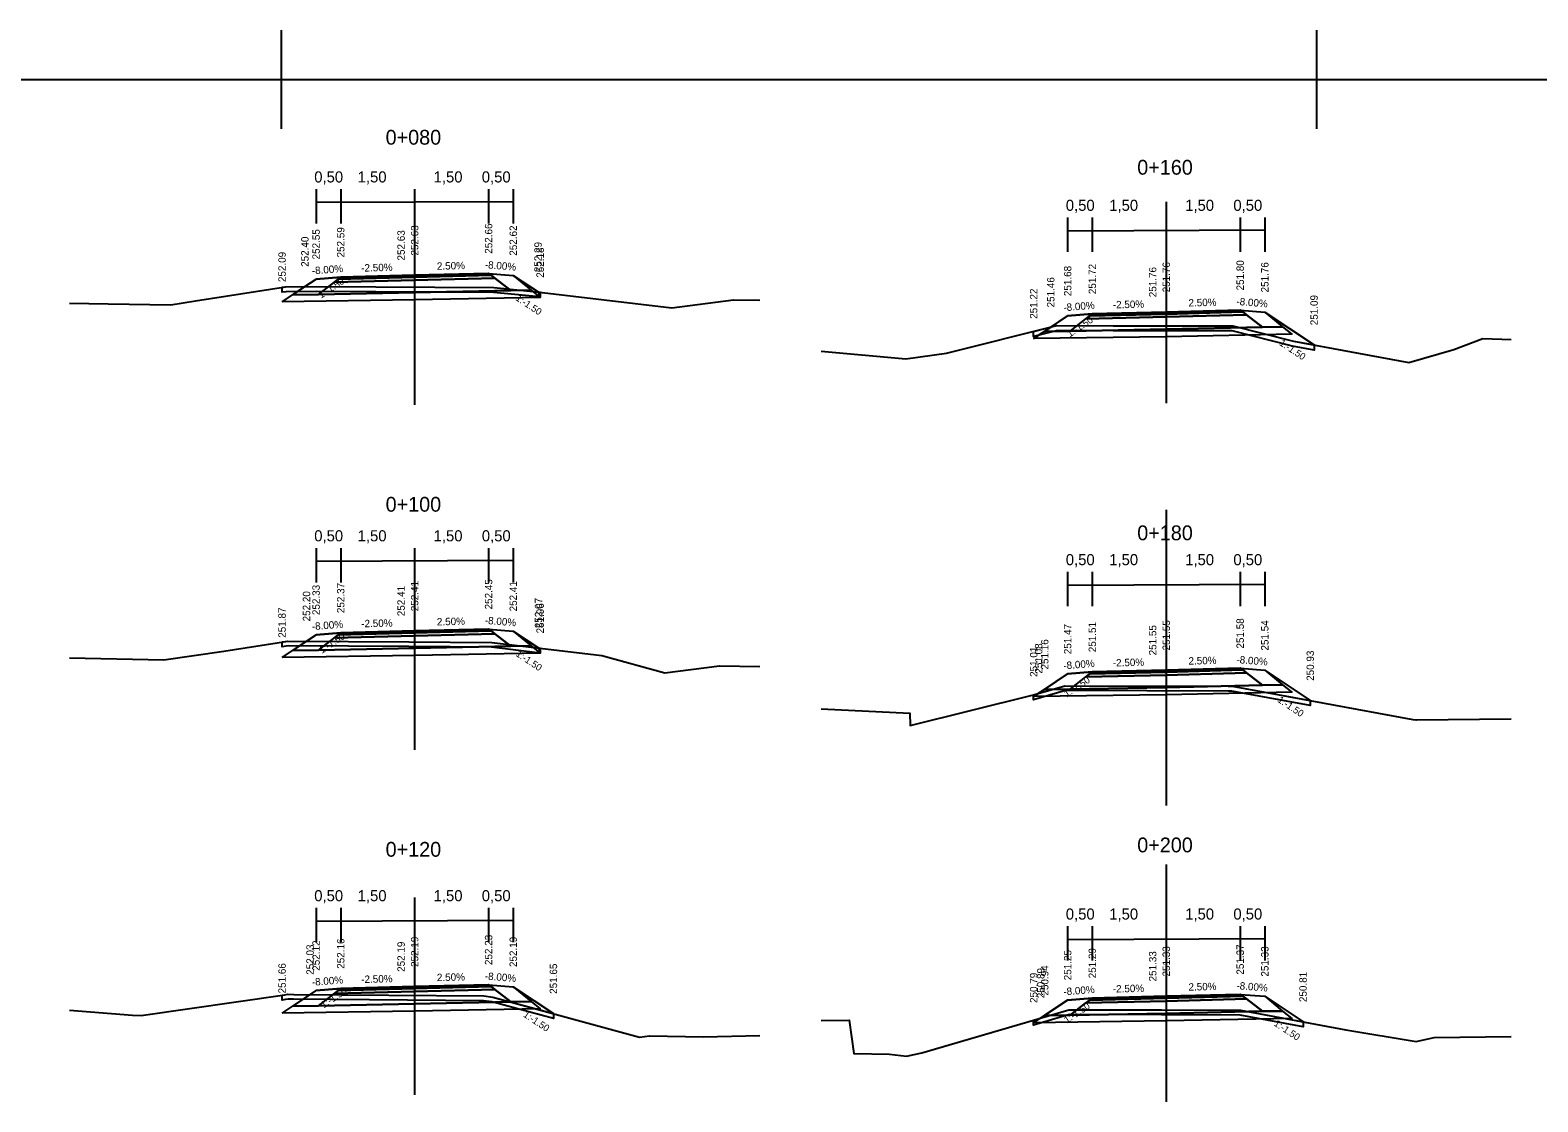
# Model space of a CAD drawing. Extents: x -552501 to -552394, y -1029983 to -1029892.
# Drawn here: x -552483.85 to -552453.26, y -1029914.09 to -1029892.35 of the extents above; entities that cross this region are included whole.
import ezdxf

# ---------------------------------------------------------------- set-up
doc = ezdxf.new("R2010")
doc.units = 0
for name, color, linetype in [('1', 7, 'Continuous'), ('16', 7, 'Continuous'), ('60', 7, 'Continuous'), ('9', 7, 'Continuous'), ('FORMATY', 7, 'Continuous'), ('Implicitní', 7, 'Continuous'), ('rámeček', 7, 'Continuous')]:
    doc.layers.add(name, color=color, linetype=linetype)

msp = doc.modelspace()

# ---------------------------------------------------------------- linework, layer by layer
for points in [[(-552478.74, -1029897.861), (-552478.277, -1029897.552), (-552478.05, -1029897.401), (-552477.55, -1029897.361), (-552476.05, -1029897.323), (-552474.55, -1029897.286), (-552474.05, -1029897.326), (-552473.547, -1029897.661), (-552473.504, -1029897.773)], [(-552483.05, -1029897.887), (-552482.271, -1029897.904), (-552480.995, -1029897.92), (-552480.495, -1029897.843), (-552478.667, -1029897.556), (-552478.034, -1029897.549), (-552474.445, -1029897.572), (-552473.576, -1029897.658), (-552470.831, -1029897.981), (-552469.585, -1029897.822), (-552469.05, -1029897.83)], [(-552463.493, -1029898.606), (-552463.146, -1029898.375), (-552462.803, -1029898.146), (-552462.303, -1029898.106), (-552460.803, -1029898.069), (-552459.303, -1029898.031), (-552458.803, -1029898.071), (-552457.804, -1029898.737)], [(-552467.803, -1029898.865), (-552466.089, -1029899.02), (-552465.26, -1029898.901), (-552463.022, -1029898.344), (-552461.878, -1029898.352), (-552459.452, -1029898.349), (-552458.221, -1029898.66), (-552455.879, -1029899.092), (-552454.971, -1029898.828), (-552454.377, -1029898.604), (-552453.803, -1029898.623)], [(-552478.74, -1029905.077), (-552478.244, -1029904.745), (-552478.05, -1029904.617), (-552477.55, -1029904.577), (-552476.05, -1029904.539), (-552474.55, -1029904.502), (-552474.05, -1029904.542), (-552473.537, -1029904.883), (-552473.504, -1029904.989)], [(-552483.05, -1029905.081), (-552481.14, -1029905.123), (-552479.921, -1029904.948), (-552478.626, -1029904.743), (-552476.165, -1029904.757), (-552474.484, -1029904.771), (-552472.254, -1029905.035), (-552470.974, -1029905.386), (-552469.867, -1029905.246), (-552469.05, -1029905.26)], [(-552463.493, -1029905.871), (-552463.392, -1029905.804), (-552463.268, -1029905.721), (-552462.803, -1029905.411), (-552462.303, -1029905.371), (-552460.803, -1029905.334), (-552459.303, -1029905.296), (-552458.803, -1029905.336), (-552457.881, -1029905.951)], [(-552467.803, -1029906.117), (-552466.006, -1029906.205), (-552465.997, -1029906.458), (-552463.523, -1029905.843), (-552462.863, -1029905.649), (-552459.545, -1029905.659), (-552459.464, -1029905.659), (-552455.799, -1029906.336), (-552455.741, -1029906.345), (-552455.726, -1029906.342), (-552453.803, -1029906.319)], [(-552483.05, -1029912.23), (-552481.776, -1029912.335), (-552481.601, -1029912.339), (-552478.683, -1029911.92), (-552478.621, -1029911.91), (-552478.504, -1029911.911), (-552474.644, -1029911.943), (-552474.462, -1029911.965), (-552471.489, -1029912.779), (-552471.283, -1029912.753), (-552470.189, -1029912.771), (-552469.05, -1029912.746)], [(-552478.74, -1029912.292), (-552478.172, -1029911.914), (-552478.05, -1029911.832), (-552477.55, -1029911.792), (-552476.05, -1029911.755), (-552474.55, -1029911.717), (-552474.05, -1029911.757), (-552473.235, -1029912.301)], [(-552463.493, -1029912.486), (-552463.348, -1029912.39), (-552463.268, -1029912.336), (-552462.803, -1029912.026), (-552462.303, -1029911.986), (-552460.803, -1029911.949), (-552459.303, -1029911.911), (-552458.803, -1029911.951), (-552458.028, -1029912.468)], [(-552467.803, -1029912.44), (-552467.237, -1029912.435), (-552467.138, -1029913.113), (-552466.415, -1029913.124), (-552466.069, -1029913.166), (-552465.761, -1029913.098), (-552462.778, -1029912.222), (-552460.901, -1029912.228), (-552459.294, -1029912.234), (-552457.16, -1029912.628), (-552455.73, -1029912.871), (-552455.37, -1029912.785), (-552453.803, -1029912.766)]]:
    msp.add_lwpolyline(points)
for points in [[(-552477.55, -1029897.361), (-552478.05, -1029897.401), (-552478.515, -1029897.711), (-552478.001, -1029897.711)], [(-552478.001, -1029897.711), (-552477.679, -1029897.461), (-552476.051, -1029897.423), (-552474.422, -1029897.38), (-552474.1, -1029897.63), (-552476.051, -1029897.673)], [(-552476.051, -1029897.363), (-552477.601, -1029897.401), (-552477.679, -1029897.461), (-552476.051, -1029897.423), (-552474.422, -1029897.38), (-552474.499, -1029897.32), (-552476.051, -1029897.363), (-552474.499, -1029897.32), (-552474.55, -1029897.286), (-552476.05, -1029897.323), (-552477.55, -1029897.361), (-552477.601, -1029897.401)], [(-552477.679, -1029897.461), (-552477.601, -1029897.401), (-552476.051, -1029897.363), (-552474.499, -1029897.32), (-552474.422, -1029897.38), (-552476.051, -1029897.423)], [(-552474.55, -1029897.286), (-552474.05, -1029897.326), (-552473.689, -1029897.623), (-552474.1, -1029897.63), (-552474.422, -1029897.38), (-552474.499, -1029897.32)], [(-552478.74, -1029897.567), (-552478.667, -1029897.556), (-552478.034, -1029897.549), (-552474.445, -1029897.572), (-552473.576, -1029897.658), (-552473.504, -1029897.666), (-552473.504, -1029897.767), (-552473.587, -1029897.757), (-552474.451, -1029897.672), (-552478.034, -1029897.649), (-552478.659, -1029897.656), (-552478.74, -1029897.669)], [(-552478.74, -1029897.861), (-552478.515, -1029897.711), (-552478.001, -1029897.711), (-552476.051, -1029897.673), (-552474.1, -1029897.63), (-552473.689, -1029897.623), (-552473.504, -1029897.773), (-552476.051, -1029897.823)], [(-552462.303, -1029898.106), (-552462.803, -1029898.146), (-552463.268, -1029898.456), (-552462.754, -1029898.456)], [(-552462.754, -1029898.456), (-552462.432, -1029898.206), (-552460.804, -1029898.169), (-552459.175, -1029898.125), (-552458.853, -1029898.375), (-552460.804, -1029898.419)], [(-552460.804, -1029898.109), (-552462.354, -1029898.146), (-552462.432, -1029898.206), (-552460.804, -1029898.169), (-552459.175, -1029898.125), (-552459.252, -1029898.065), (-552460.804, -1029898.109), (-552459.252, -1029898.065), (-552459.303, -1029898.031), (-552460.803, -1029898.069), (-552462.303, -1029898.106), (-552462.354, -1029898.146)], [(-552462.432, -1029898.206), (-552462.354, -1029898.146), (-552460.804, -1029898.109), (-552459.252, -1029898.065), (-552459.175, -1029898.125), (-552460.804, -1029898.169)], [(-552459.303, -1029898.031), (-552458.803, -1029898.071), (-552458.442, -1029898.369), (-552458.853, -1029898.375), (-552459.175, -1029898.125), (-552459.252, -1029898.065)], [(-552463.493, -1029898.461), (-552463.022, -1029898.344), (-552461.878, -1029898.352), (-552459.452, -1029898.349), (-552458.221, -1029898.66), (-552457.804, -1029898.737), (-552457.804, -1029898.839), (-552458.242, -1029898.758), (-552459.465, -1029898.449), (-552461.878, -1029898.452), (-552463.011, -1029898.444), (-552463.493, -1029898.564)], [(-552463.493, -1029898.606), (-552463.268, -1029898.456), (-552462.754, -1029898.456), (-552460.804, -1029898.419), (-552458.853, -1029898.375), (-552458.442, -1029898.369), (-552458.257, -1029898.519), (-552460.804, -1029898.569)], [(-552476.051, -1029904.579), (-552477.601, -1029904.617), (-552477.679, -1029904.677), (-552476.051, -1029904.639), (-552474.422, -1029904.596), (-552474.499, -1029904.536), (-552476.051, -1029904.579), (-552474.499, -1029904.536), (-552474.55, -1029904.502), (-552476.05, -1029904.539), (-552477.55, -1029904.577), (-552477.601, -1029904.617)], [(-552477.679, -1029904.677), (-552477.601, -1029904.617), (-552476.051, -1029904.579), (-552474.499, -1029904.536), (-552474.422, -1029904.596), (-552476.051, -1029904.639)], [(-552474.55, -1029904.502), (-552474.05, -1029904.542), (-552473.689, -1029904.839), (-552474.1, -1029904.846), (-552474.422, -1029904.596), (-552474.499, -1029904.536)], [(-552478.74, -1029904.761), (-552478.626, -1029904.743), (-552476.165, -1029904.757), (-552474.484, -1029904.771), (-552473.504, -1029904.887), (-552473.504, -1029904.988), (-552474.49, -1029904.871), (-552476.166, -1029904.857), (-552478.618, -1029904.843), (-552478.74, -1029904.863)], [(-552478.74, -1029905.077), (-552478.515, -1029904.927), (-552478.001, -1029904.927), (-552476.051, -1029904.889), (-552474.1, -1029904.846), (-552473.689, -1029904.839), (-552473.504, -1029904.989), (-552476.051, -1029905.039)], [(-552477.55, -1029904.577), (-552478.05, -1029904.617), (-552478.515, -1029904.927), (-552478.001, -1029904.927)], [(-552478.001, -1029904.927), (-552477.679, -1029904.677), (-552476.051, -1029904.639), (-552474.422, -1029904.596), (-552474.1, -1029904.846), (-552476.051, -1029904.889)], [(-552462.303, -1029905.371), (-552462.803, -1029905.411), (-552463.268, -1029905.721), (-552462.754, -1029905.721)], [(-552462.754, -1029905.721), (-552462.432, -1029905.471), (-552460.804, -1029905.434), (-552459.175, -1029905.39), (-552458.853, -1029905.64), (-552460.804, -1029905.684)], [(-552460.804, -1029905.374), (-552462.354, -1029905.411), (-552462.432, -1029905.471), (-552460.804, -1029905.434), (-552459.175, -1029905.39), (-552459.252, -1029905.33), (-552460.804, -1029905.374), (-552459.252, -1029905.33), (-552459.303, -1029905.296), (-552460.803, -1029905.334), (-552462.303, -1029905.371), (-552462.354, -1029905.411)], [(-552462.432, -1029905.471), (-552462.354, -1029905.411), (-552460.804, -1029905.374), (-552459.252, -1029905.33), (-552459.175, -1029905.39), (-552460.804, -1029905.434)], [(-552459.303, -1029905.296), (-552458.803, -1029905.336), (-552458.442, -1029905.634), (-552458.853, -1029905.64), (-552459.175, -1029905.39), (-552459.252, -1029905.33)], [(-552463.493, -1029905.871), (-552463.268, -1029905.721), (-552462.754, -1029905.721), (-552460.804, -1029905.684), (-552458.853, -1029905.64), (-552458.442, -1029905.634), (-552458.257, -1029905.784), (-552460.804, -1029905.834)], [(-552463.493, -1029905.834), (-552462.863, -1029905.649), (-552459.545, -1029905.659), (-552459.464, -1029905.659), (-552457.881, -1029905.951), (-552457.881, -1029906.053), (-552459.473, -1029905.759), (-552459.545, -1029905.759), (-552462.849, -1029905.749), (-552463.493, -1029905.938)], [(-552478.74, -1029911.928), (-552478.683, -1029911.92), (-552478.621, -1029911.91), (-552478.504, -1029911.911), (-552474.644, -1029911.943), (-552474.462, -1029911.965), (-552473.235, -1029912.301), (-552473.235, -1029912.404), (-552474.481, -1029912.063), (-552474.65, -1029912.043), (-552478.505, -1029912.011), (-552478.614, -1029912.01), (-552478.668, -1029912.019), (-552478.74, -1029912.029)], [(-552477.55, -1029911.792), (-552478.05, -1029911.832), (-552478.515, -1029912.142), (-552478.001, -1029912.142)], [(-552478.001, -1029912.142), (-552477.679, -1029911.892), (-552476.051, -1029911.855), (-552474.422, -1029911.811), (-552474.1, -1029912.061), (-552476.051, -1029912.105)], [(-552476.051, -1029911.795), (-552477.601, -1029911.832), (-552477.679, -1029911.892), (-552476.051, -1029911.855), (-552474.422, -1029911.811), (-552474.499, -1029911.751), (-552476.051, -1029911.795), (-552474.499, -1029911.751), (-552474.55, -1029911.717), (-552476.05, -1029911.755), (-552477.55, -1029911.792), (-552477.601, -1029911.832)], [(-552477.679, -1029911.892), (-552477.601, -1029911.832), (-552476.051, -1029911.795), (-552474.499, -1029911.751), (-552474.422, -1029911.811), (-552476.051, -1029911.855)], [(-552474.55, -1029911.717), (-552474.05, -1029911.757), (-552473.689, -1029912.055), (-552474.1, -1029912.061), (-552474.422, -1029911.811), (-552474.499, -1029911.751)], [(-552460.804, -1029911.989), (-552462.354, -1029912.026), (-552462.432, -1029912.086), (-552460.804, -1029912.049), (-552459.175, -1029912.005), (-552459.252, -1029911.945), (-552460.804, -1029911.989), (-552459.252, -1029911.945), (-552459.303, -1029911.911), (-552460.803, -1029911.949), (-552462.303, -1029911.986), (-552462.354, -1029912.026)], [(-552459.303, -1029911.911), (-552458.803, -1029911.951), (-552458.442, -1029912.249), (-552458.853, -1029912.255), (-552459.175, -1029912.005), (-552459.252, -1029911.945)], [(-552478.74, -1029912.292), (-552478.515, -1029912.142), (-552478.001, -1029912.142), (-552476.051, -1029912.105), (-552474.1, -1029912.061), (-552473.689, -1029912.055), (-552473.504, -1029912.205), (-552476.051, -1029912.255)], [(-552462.303, -1029911.986), (-552462.803, -1029912.026), (-552463.268, -1029912.336), (-552462.754, -1029912.336)], [(-552462.754, -1029912.336), (-552462.432, -1029912.086), (-552460.804, -1029912.049), (-552459.175, -1029912.005), (-552458.853, -1029912.255), (-552460.804, -1029912.299)], [(-552462.432, -1029912.086), (-552462.354, -1029912.026), (-552460.804, -1029911.989), (-552459.252, -1029911.945), (-552459.175, -1029912.005), (-552460.804, -1029912.049)], [(-552463.493, -1029912.432), (-552462.778, -1029912.222), (-552460.901, -1029912.228), (-552459.294, -1029912.234), (-552458.028, -1029912.468), (-552458.028, -1029912.569), (-552459.303, -1029912.334), (-552460.902, -1029912.328), (-552462.764, -1029912.322), (-552463.493, -1029912.536)], [(-552463.493, -1029912.486), (-552463.268, -1029912.336), (-552462.754, -1029912.336), (-552460.804, -1029912.299), (-552458.853, -1029912.255), (-552458.442, -1029912.249), (-552458.257, -1029912.399), (-552460.804, -1029912.449)]]:
    msp.add_lwpolyline(points, close=True)
at = {"layer": '60'}
for p, q in [((-552476.05, -1029895.949), (-552476.05, -1029899.949)), ((-552460.803, -1029895.831), (-552460.803, -1029899.916)), ((-552460.803, -1029902.082), (-552460.803, -1029908.082)), ((-552476.05, -1029902.949), (-552476.05, -1029906.949)), ((-552460.803, -1029909.279), (-552460.803, -1029914.092)), ((-552476.05, -1029909.949), (-552476.05, -1029913.949))]:
    msp.add_line(p, q, dxfattribs=at)
at = {"layer": '9'}
for p, q in [((-552478.05, -1029895.575), (-552478.05, -1029896.273)), ((-552477.55, -1029895.575), (-552477.55, -1029896.273)), ((-552476.05, -1029895.575), (-552476.05, -1029897.075)), ((-552474.55, -1029895.575), (-552474.55, -1029896.273)), ((-552474.05, -1029895.575), (-552474.05, -1029896.273)), ((-552462.803, -1029896.151), (-552462.803, -1029896.849)), ((-552462.303, -1029896.151), (-552462.303, -1029896.849)), ((-552460.803, -1029896.151), (-552460.803, -1029897.651)), ((-552459.303, -1029896.151), (-552459.303, -1029896.849)), ((-552458.803, -1029896.151), (-552458.803, -1029896.849)), ((-552478.05, -1029902.856), (-552478.05, -1029903.554)), ((-552477.55, -1029902.856), (-552477.55, -1029903.554)), ((-552476.05, -1029902.856), (-552476.05, -1029904.356)), ((-552474.55, -1029902.856), (-552474.55, -1029903.554)), ((-552474.05, -1029902.856), (-552474.05, -1029903.554)), ((-552462.803, -1029903.34), (-552462.803, -1029904.038)), ((-552462.303, -1029903.34), (-552462.303, -1029904.038)), ((-552460.803, -1029903.34), (-552460.803, -1029904.84)), ((-552459.303, -1029903.34), (-552459.303, -1029904.038)), ((-552458.803, -1029903.34), (-552458.803, -1029904.038)), ((-552478.05, -1029910.157), (-552478.05, -1029910.854)), ((-552477.55, -1029910.157), (-552477.55, -1029910.854)), ((-552476.05, -1029910.157), (-552476.05, -1029911.657)), ((-552474.55, -1029910.157), (-552474.55, -1029910.854)), ((-552474.05, -1029910.157), (-552474.05, -1029910.854)), ((-552462.803, -1029910.529), (-552462.803, -1029911.227)), ((-552462.303, -1029910.529), (-552462.303, -1029911.227)), ((-552460.803, -1029910.529), (-552460.803, -1029912.029)), ((-552459.303, -1029910.529), (-552459.303, -1029911.227)), ((-552458.803, -1029910.529), (-552458.803, -1029911.227))]:
    msp.add_line(p, q, dxfattribs=at)
at = {"layer": 'FORMATY'}
for p, q in [((-552478.755, -1029892.35), (-552478.755, -1029894.35)), ((-552457.755, -1029892.35), (-552457.755, -1029894.35)), ((-552479.755, -1029893.35), (-552477.755, -1029893.35)), ((-552458.755, -1029893.35), (-552456.755, -1029893.35))]:
    msp.add_line(p, q, dxfattribs=at)
at = {"layer": 'Implicitní'}
for p, q in [((-552478.04, -1029895.843), (-552474.05, -1029895.825)), ((-552462.793, -1029896.419), (-552458.803, -1029896.401)), ((-552478.04, -1029903.123), (-552474.05, -1029903.106)), ((-552462.793, -1029903.608), (-552458.803, -1029903.59)), ((-552478.04, -1029910.424), (-552474.05, -1029910.407)), ((-552462.793, -1029910.796), (-552458.803, -1029910.779))]:
    msp.add_line(p, q, dxfattribs=at)
at = {"layer": 'rámeček'}
msp.add_line((-552499.755, -1029893.35), (-552394.755, -1029893.35), dxfattribs=at)

# ---------------------------------------------------------------- texts
for rotation, p in [(33.6902, (-552477.947, -1029897.801)), (326.3098, (-552474.015, -1029897.818)), (33.6902, (-552462.758, -1029898.585)), (326.3098, (-552458.52, -1029898.729)), (33.6902, (-552477.931, -1029905.005)), (326.3098, (-552474.01, -1029905.037)), (33.6902, (-552462.819, -1029905.891)), (326.3098, (-552458.558, -1029905.968)), (33.6902, (-552477.895, -1029912.198)), (33.6902, (-552462.819, -1029912.506)), (326.3098, (-552473.859, -1029912.354)), (326.3098, (-552458.632, -1029912.534))]:
    msp.add_text('1:-1.50', height=0.14, rotation=rotation).set_placement(p)
at = {"layer": '1'}
for s, p in [('0+080', (-552476.639, -1029894.673)), ('0+160', (-552461.391, -1029895.282)), ('0+100', (-552476.639, -1029902.119)), ('0+180', (-552461.391, -1029902.698)), ('0+120', (-552476.639, -1029909.119)), ('0+200', (-552461.391, -1029909.03))]:
    msp.add_text(s, height=0.3, dxfattribs=at).set_placement(p)
at = {"layer": '16'}
for s, p in [('0,50', (-552478.087, -1029895.44)), ('1,50', (-552477.206, -1029895.44)), ('1,50', (-552475.665, -1029895.44)), ('0,50', (-552474.688, -1029895.44)), ('0,50', (-552462.84, -1029896.016)), ('1,50', (-552461.959, -1029896.016)), ('1,50', (-552460.418, -1029896.016)), ('0,50', (-552459.441, -1029896.016)), ('0,50', (-552478.087, -1029902.721)), ('1,50', (-552477.206, -1029902.721)), ('1,50', (-552475.665, -1029902.721)), ('0,50', (-552474.687, -1029902.721)), ('0,50', (-552462.84, -1029903.205)), ('1,50', (-552461.959, -1029903.205)), ('1,50', (-552460.418, -1029903.205)), ('0,50', (-552459.441, -1029903.205)), ('0,50', (-552478.087, -1029910.022)), ('1,50', (-552477.206, -1029910.022)), ('1,50', (-552475.665, -1029910.022)), ('0,50', (-552474.688, -1029910.022)), ('0,50', (-552462.84, -1029910.394)), ('1,50', (-552461.959, -1029910.394)), ('1,50', (-552460.418, -1029910.394)), ('0,50', (-552459.441, -1029910.394))]:
    msp.add_text(s, height=0.225, dxfattribs=at).set_placement(p)
for s, rotation, p in [('252.66', 90, (-552474.475, -1029896.886)), ('252.40', 90, (-552478.202, -1029897.152)), ('252.55', 90, (-552477.975, -1029897.001)), ('252.59', 90, (-552477.475, -1029896.961)), ('252.63', 90, (-552476.25, -1029897.023)), ('252.63', 90, (-552475.975, -1029896.923)), ('252.62', 90, (-552473.975, -1029896.926)), ('252.09', 90, (-552478.665, -1029897.461)), ('252.29', 90, (-552473.472, -1029897.261)), ('252.18', 90, (-552473.429, -1029897.373)), ('-8.00%', 4.5739, (-552478.131, -1029897.307)), ('-2.50%', 1.4321, (-552477.132, -1029897.25)), ('2.50%', 1.4321, (-552475.597, -1029897.212)), ('-8.00%', 355.4261, (-552474.631, -1029897.179)), ('251.68', 90, (-552462.728, -1029897.746)), ('251.72', 90, (-552462.228, -1029897.706)), ('251.76', 90, (-552461.003, -1029897.769)), ('251.76', 90, (-552460.728, -1029897.669)), ('251.80', 90, (-552459.228, -1029897.631)), ('251.76', 90, (-552458.728, -1029897.671)), ('251.46', 90, (-552463.071, -1029897.975)), ('251.22', 90, (-552463.418, -1029898.206)), ('-2.50%', 1.4321, (-552461.885, -1029897.996)), ('2.50%', 1.4321, (-552460.35, -1029897.957)), ('-8.00%', 355.4261, (-552459.384, -1029897.925)), ('251.09', 90, (-552457.729, -1029898.337)), ('-8.00%', 4.5739, (-552462.884, -1029898.053)), ('252.33', 90, (-552477.975, -1029904.217)), ('252.37', 90, (-552477.475, -1029904.177)), ('252.41', 90, (-552476.25, -1029904.239)), ('252.41', 90, (-552475.975, -1029904.139)), ('252.45', 90, (-552474.475, -1029904.102)), ('252.41', 90, (-552473.975, -1029904.142)), ('252.20', 90, (-552478.169, -1029904.345)), ('252.07', 90, (-552473.462, -1029904.483)), ('251.87', 90, (-552478.665, -1029904.677)), ('2.50%', 1.4321, (-552475.597, -1029904.428)), ('-8.00%', 355.4261, (-552474.631, -1029904.395)), ('251.96', 90, (-552473.429, -1029904.589)), ('-8.00%', 4.5739, (-552478.131, -1029904.523)), ('-2.50%', 1.4321, (-552477.132, -1029904.466)), ('251.47', 90, (-552462.728, -1029905.011)), ('251.51', 90, (-552462.228, -1029904.971)), ('251.55', 90, (-552461.003, -1029905.034)), ('251.55', 90, (-552460.728, -1029904.934)), ('251.58', 90, (-552459.228, -1029904.896)), ('251.54', 90, (-552458.728, -1029904.936)), ('251.01', 90, (-552463.418, -1029905.471)), ('251.08', 90, (-552463.317, -1029905.404)), ('251.16', 90, (-552463.193, -1029905.321)), ('-8.00%', 4.5739, (-552462.884, -1029905.318)), ('-2.50%', 1.4321, (-552461.885, -1029905.261)), ('2.50%', 1.4321, (-552460.35, -1029905.223)), ('-8.00%', 355.4261, (-552459.384, -1029905.19)), ('250.93', 90, (-552457.806, -1029905.551)), ('252.03', 90, (-552478.097, -1029911.514)), ('252.12', 90, (-552477.975, -1029911.432)), ('252.16', 90, (-552477.475, -1029911.392)), ('252.19', 90, (-552476.25, -1029911.455)), ('252.19', 90, (-552475.975, -1029911.355)), ('252.23', 90, (-552474.475, -1029911.317)), ('252.19', 90, (-552473.975, -1029911.357)), ('251.29', 90, (-552462.228, -1029911.586)), ('251.33', 90, (-552460.728, -1029911.549)), ('251.37', 90, (-552459.228, -1029911.511)), ('251.33', 90, (-552458.728, -1029911.551)), ('251.66', 90, (-552478.665, -1029911.892)), ('251.65', 90, (-552473.16, -1029911.901)), ('251.25', 90, (-552462.728, -1029911.626)), ('251.33', 90, (-552461.003, -1029911.649)), ('-8.00%', 4.5739, (-552478.131, -1029911.739)), ('-2.50%', 1.4321, (-552477.132, -1029911.682)), ('2.50%', 1.4321, (-552475.597, -1029911.644)), ('-8.00%', 355.4261, (-552474.631, -1029911.611)), ('250.79', 90, (-552463.418, -1029912.086)), ('250.89', 90, (-552463.273, -1029911.99)), ('250.94', 90, (-552463.193, -1029911.936)), ('250.81', 90, (-552457.953, -1029912.068)), ('-8.00%', 4.5739, (-552462.884, -1029911.933)), ('-2.50%', 1.4321, (-552461.885, -1029911.876)), ('2.50%', 1.4321, (-552460.35, -1029911.837)), ('-8.00%', 355.4261, (-552459.384, -1029911.805))]:
    msp.add_text(s, height=0.15, rotation=rotation, dxfattribs=at).set_placement(p)

doc.saveas('drawing.dxf')
